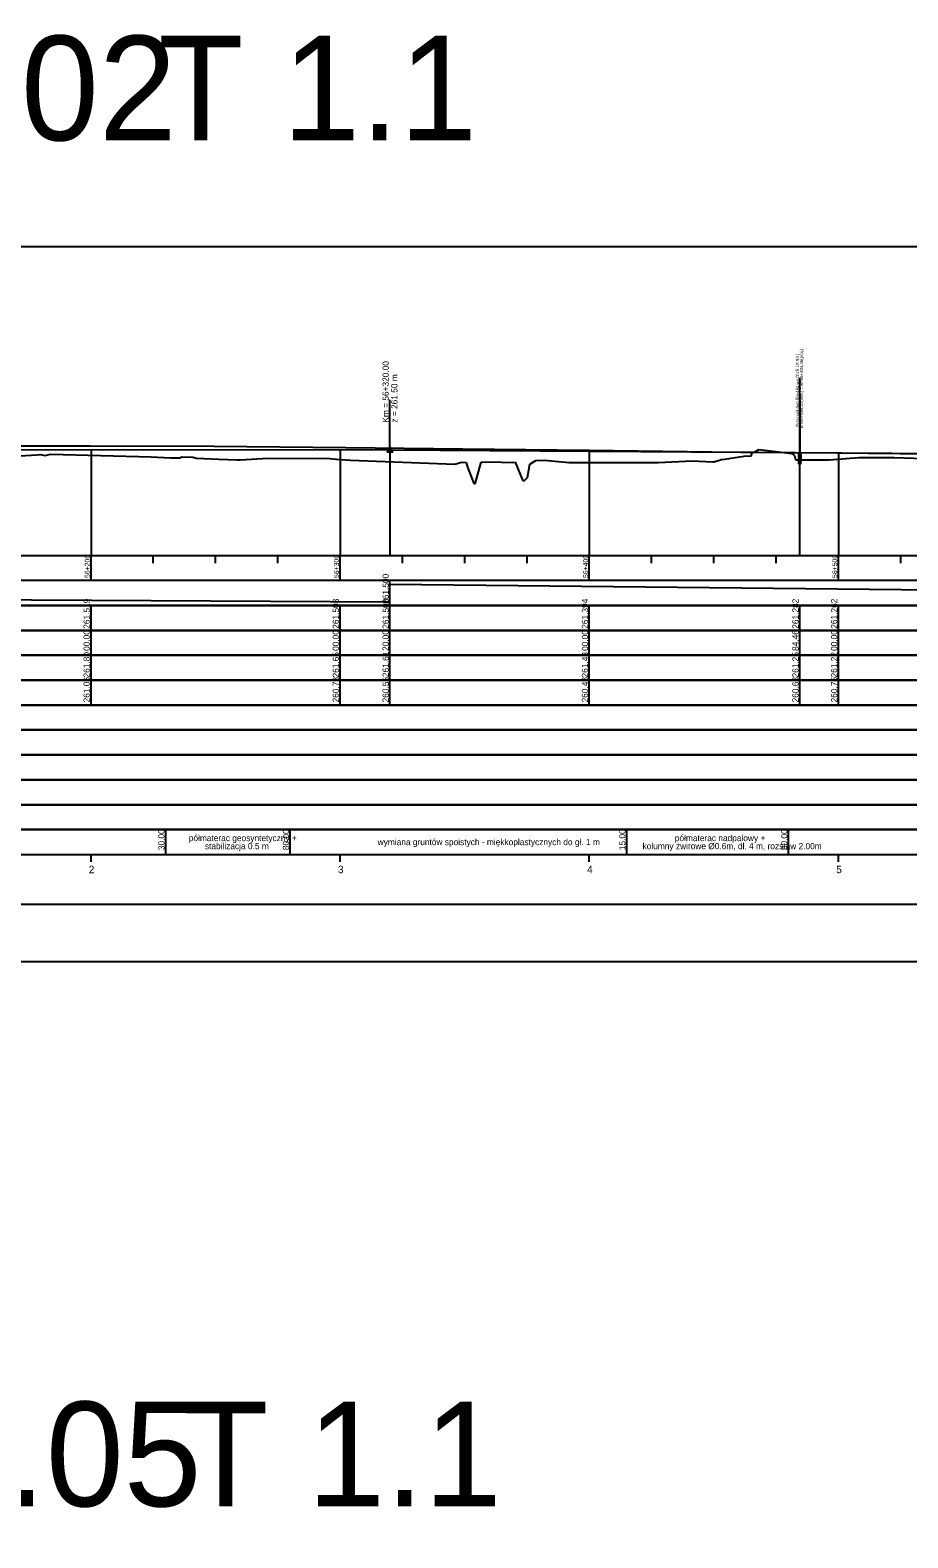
# Model space of a CAD drawing. Extents: x 6445630 to 6518227, y 5499240 to 5511716.
# Drawn here: x 6455407 to 6455759, y 5508735 to 5509341 of the extents above; entities that cross this region are included whole.
import ezdxf

# ---------------------------------------------------------------- set-up
doc = ezdxf.new("R2010")
doc.units = 0
for name, color, linetype in [('Default', 7, 'Continuous'), ('TOR_PROF-obiekty+opisy', 7, 'Continuous'), ('TOR_PROF-opisy pomocnicze', 7, 'Continuous'), ('TOR_PROF-tabelka-geometria T1', 7, 'Continuous'), ('TOR_PROF-tabelka-kilometracja', 7, 'Continuous'), ('TOR_PROF-tabelka-odleglosci T1', 7, 'Continuous'), ('TOR_PROF-tabelka-pochylenia proj T1', 7, 'Continuous'), ('TOR_PROF-tabelka-rodzaj rowu T1', 7, 'Continuous'), ('TOR_PROF-tabelka-rowyT1', 7, 'Continuous'), ('TOR_PROF-tabelka-rurociagi T1', 7, 'Continuous'), ('TOR_PROF-tabelka-rzedne istn T1', 7, 'Continuous'), ('TOR_PROF-tabelka-rzedne proj T1', 7, 'Continuous'), ('TOR_PROF-tabelka-teren istniejacy T1', 7, 'Continuous'), ('TOR_PROF-tabelka-warstwa ochronna T1', 7, 'Continuous'), ('TOR_PROF-tor istniejacy T1', 7, 'Continuous'), ('TOR_PROF-tor projektowany', 7, 'Continuous'), ('TOR_PROF-uklad odniesienia', 7, 'Continuous'), ('TOR_PROF-warstwa ochronna', 7, 'Continuous'), ('TOR_RAMKI-dodatkowe3', 7, 'Continuous'), ('TOR_RAMKI-MASKA WYCIECIA', 7, 'Continuous')]:
    doc.layers.add(name, color=color, linetype=linetype)

msp = doc.modelspace()

# ---------------------------------------------------------------- linework, layer by layer
at = {"layer": 'TOR_PROF-obiekty+opisy'}
for p, q in [((6455715.67, 5509129.74), (6455715.67, 5509201.14)), ((6455715.67, 5509192.14), (6455715.67, 5509171.14))]:
    msp.add_line(p, q, dxfattribs=at)
for points in [[(6455716.14, 5509170.78), (6455715.22, 5509170.78), (6455715.22, 5509166.7), (6455716.14, 5509166.7)], [(6455716.06, 5509170.24), (6455715.31, 5509170.24), (6455715.31, 5509167.24), (6455716.06, 5509167.24)]]:
    msp.add_lwpolyline(points, close=True, dxfattribs=at)
for points in [[(6455716.14, 5509166.7), (6455716.14, 5509170.78), (6455715.22, 5509170.78), (6455715.22, 5509166.7), (6455716.14, 5509166.7)], [(6455716.06, 5509167.24), (6455715.31, 5509167.24), (6455715.31, 5509170.24), (6455716.06, 5509170.24), (6455716.06, 5509167.24)]]:
    msp.add_lwpolyline(points, dxfattribs=at)
at = {"layer": 'TOR_PROF-opisy pomocnicze'}
msp.add_line((6455551.21, 5509172.24), (6455551.21, 5509192.24), dxfattribs=at)
msp.add_line((6455551.21, 5509172.24), (6455551.21, 5509192.24), dxfattribs=at)
msp.add_lwpolyline([(6455551.21, 5509173.24), (6455552.21, 5509171.24), (6455550.21, 5509171.24)], close=True, dxfattribs=at)
msp.add_lwpolyline([(6455551.21, 5509173.24), (6455552.21, 5509171.24), (6455550.21, 5509171.24)], close=True, dxfattribs=at)
at = {"layer": 'TOR_PROF-tabelka-geometria T1'}
for points in [[(6452331.21, 5508989.74), (6462728.4, 5508989.74)], [(6452331.21, 5508989.74), (6462731.21, 5508989.74)]]:
    msp.add_lwpolyline(points, dxfattribs=at)
at = {"layer": 'TOR_PROF-tabelka-kilometracja'}
for points in [[(6455431.21, 5509006.74), (6455431.21, 5509009.74)], [(6455531.21, 5509006.74), (6455531.21, 5509009.74)], [(6455631.21, 5509006.74), (6455631.21, 5509009.74)], [(6455731.21, 5509006.74), (6455731.21, 5509009.74)]]:
    msp.add_lwpolyline(points, dxfattribs=at)
at = {"layer": 'TOR_PROF-tabelka-odleglosci T1'}
msp.add_lwpolyline([(6452331.21, 5509089.74), (6462731.21, 5509089.74), (6462731.21, 5509099.74), (6452331.21, 5509099.74)], close=True, dxfattribs=at)
for points in [[(6455431.21, 5509089.74), (6455431.21, 5509099.74)], [(6455531.21, 5509089.74), (6455531.21, 5509099.74)], [(6455551.21, 5509089.74), (6455551.21, 5509099.74)], [(6455631.21, 5509089.74), (6455631.21, 5509099.74)], [(6455715.67, 5509089.74), (6455715.67, 5509099.74)], [(6455731.21, 5509089.74), (6455731.21, 5509099.74)]]:
    msp.add_lwpolyline(points, dxfattribs=at)
at = {"layer": 'TOR_PROF-tabelka-pochylenia proj T1'}
msp.add_lwpolyline([(6452331.21, 5509109.74), (6462731.21, 5509109.74), (6462731.21, 5509119.74), (6452331.21, 5509119.74)], close=True, dxfattribs=at)
for points in [[(6454281.21, 5509118.24), (6455551.21, 5509111.24)], [(6455551.21, 5509109.74), (6455551.21, 5509119.74)], [(6455551.21, 5509118.24), (6456231.21, 5509111.24)]]:
    msp.add_lwpolyline(points, dxfattribs=at)
at = {"layer": 'TOR_PROF-tabelka-rodzaj rowu T1'}
for points in [[(6452331.21, 5509049.74), (6462731.21, 5509049.74), (6462731.21, 5509059.74), (6452331.21, 5509059.74)], [(6452331.21, 5509029.74), (6462731.21, 5509029.74), (6462731.21, 5509039.74), (6452331.21, 5509039.74)]]:
    msp.add_lwpolyline(points, close=True, dxfattribs=at)
at = {"layer": 'TOR_PROF-tabelka-rowyT1'}
msp.add_lwpolyline([(6452331.21, 5509059.74), (6462731.21, 5509059.74), (6462731.21, 5509069.74), (6452331.21, 5509069.74)], close=True, dxfattribs=at)
at = {"layer": 'TOR_PROF-tabelka-rurociagi T1'}
msp.add_lwpolyline([(6452331.21, 5509039.74), (6462731.21, 5509039.74), (6462731.21, 5509049.74), (6452331.21, 5509049.74)], close=True, dxfattribs=at)
at = {"layer": 'TOR_PROF-tabelka-rzedne istn T1'}
msp.add_lwpolyline([(6452331.21, 5509079.74), (6462731.21, 5509079.74), (6462731.21, 5509089.74), (6452331.21, 5509089.74)], close=True, dxfattribs=at)
for points in [[(6455431.21, 5509079.74), (6455431.21, 5509089.74)], [(6455531.21, 5509079.74), (6455531.21, 5509089.74)], [(6455551.21, 5509079.74), (6455551.21, 5509089.74)], [(6455631.21, 5509079.74), (6455631.21, 5509089.74)], [(6455715.67, 5509079.74), (6455715.67, 5509089.74)], [(6455731.21, 5509079.74), (6455731.21, 5509089.74)], [(6455431.21, 5509069.74), (6455431.21, 5509079.74)], [(6455431.21, 5509069.74), (6455431.21, 5509079.74)], [(6455431.21, 5509069.74), (6455431.21, 5509079.74)], [(6455431.21, 5509069.74), (6455431.21, 5509079.74)], [(6455431.21, 5509069.74), (6455431.21, 5509079.74)], [(6455531.21, 5509069.74), (6455531.21, 5509079.74)], [(6455531.21, 5509069.74), (6455531.21, 5509079.74)], [(6455531.21, 5509069.74), (6455531.21, 5509079.74)], [(6455531.21, 5509069.74), (6455531.21, 5509079.74)], [(6455531.21, 5509069.74), (6455531.21, 5509079.74)], [(6455551.21, 5509069.74), (6455551.21, 5509079.74)], [(6455631.21, 5509069.74), (6455631.21, 5509079.74)], [(6455631.21, 5509069.74), (6455631.21, 5509079.74)], [(6455631.21, 5509069.74), (6455631.21, 5509079.74)], [(6455631.21, 5509069.74), (6455631.21, 5509079.74)], [(6455631.21, 5509069.74), (6455631.21, 5509079.74)], [(6455715.67, 5509069.74), (6455715.67, 5509079.74)], [(6455731.21, 5509069.74), (6455731.21, 5509079.74)], [(6455731.21, 5509069.74), (6455731.21, 5509079.74)], [(6455731.21, 5509069.74), (6455731.21, 5509079.74)], [(6455731.21, 5509069.74), (6455731.21, 5509079.74)], [(6455731.21, 5509069.74), (6455731.21, 5509079.74)]]:
    msp.add_lwpolyline(points, dxfattribs=at)
at = {"layer": 'TOR_PROF-tabelka-rzedne proj T1'}
msp.add_lwpolyline([(6452331.21, 5509099.74), (6462731.21, 5509099.74), (6462731.21, 5509109.74), (6452331.21, 5509109.74)], close=True, dxfattribs=at)
for points in [[(6455431.21, 5509099.74), (6455431.21, 5509109.74)], [(6455531.21, 5509099.74), (6455531.21, 5509109.74)], [(6455551.21, 5509099.74), (6455551.21, 5509109.74)], [(6455631.21, 5509099.74), (6455631.21, 5509109.74)], [(6455715.67, 5509099.74), (6455715.67, 5509109.74)], [(6455731.21, 5509099.74), (6455731.21, 5509109.74)]]:
    msp.add_lwpolyline(points, dxfattribs=at)
at = {"layer": 'TOR_PROF-tabelka-teren istniejacy T1'}
msp.add_lwpolyline([(6452331.21, 5509069.74), (6462731.21, 5509069.74), (6462731.21, 5509079.74), (6452331.21, 5509079.74)], close=True, dxfattribs=at)
msp.add_lwpolyline([(6452331.21, 5509069.74), (6462731.21, 5509069.74), (6462731.21, 5509079.74), (6452331.21, 5509079.74)], close=True, dxfattribs=at)
msp.add_lwpolyline([(6452331.21, 5509069.74), (6462731.21, 5509069.74), (6462731.21, 5509079.74), (6452331.21, 5509079.74)], close=True, dxfattribs=at)
msp.add_lwpolyline([(6452331.21, 5509069.74), (6462731.21, 5509069.74), (6462731.21, 5509079.74), (6452331.21, 5509079.74)], close=True, dxfattribs=at)
msp.add_lwpolyline([(6452331.21, 5509069.74), (6462731.21, 5509069.74), (6462731.21, 5509079.74), (6452331.21, 5509079.74)], close=True, dxfattribs=at)
at = {"layer": 'TOR_PROF-tabelka-warstwa ochronna T1'}
msp.add_lwpolyline([(6452331.21, 5509019.74), (6462731.21, 5509019.74), (6462731.21, 5509029.74), (6452331.21, 5509029.74)], close=True, dxfattribs=at)
at = {"layer": 'TOR_PROF-tor istniejacy T1'}
msp.add_lwpolyline([(6455781.2, 5509170.34), (6455730.52, 5509170.84), (6455680.26, 5509171.29), (6455631.15, 5509171.89), (6455580.46, 5509172.44), (6455533.44, 5509172.99), (6455480.48, 5509173.54), (6455430.92, 5509173.74), (6455379.79, 5509173.69), (6455329.04, 5509173.64), (6455279.53, 5509173.54), (6455230.64, 5509173.49), (6455180.11, 5509173.44), (6455131.36, 5509173.34), (6455080.92, 5509173.34), (6455031.47, 5509173.29)], dxfattribs=at)
at = {"layer": 'TOR_PROF-tor projektowany'}
for p, q in [((6454281.21, 5509173.24), (6455551.21, 5509172.24)), ((6454281.21, 5509173.24), (6455551.21, 5509172.24)), ((6455551.21, 5509172.24), (6456164.22, 5509168.18)), ((6455551.21, 5509172.24), (6456231.21, 5509167.74))]:
    msp.add_line(p, q, dxfattribs=at)
for points in [[(6455431.21, 5509172.33), (6455431.21, 5509134.74), (6455431.21, 5509129.74), (6455431.21, 5509129.74)], [(6455431.21, 5509172.33), (6455431.21, 5509134.74), (6455431.21, 5509129.74), (6455431.21, 5509129.74)], [(6455531.21, 5509172.25), (6455531.21, 5509134.74), (6455531.21, 5509129.74), (6455531.21, 5509129.74)], [(6455531.21, 5509172.25), (6455531.21, 5509134.74), (6455531.21, 5509129.74), (6455531.21, 5509129.74)], [(6455551.21, 5509172.24), (6455551.21, 5509134.74), (6455551.21, 5509129.74), (6455551.21, 5509129.74)], [(6455551.21, 5509172.24), (6455551.21, 5509134.74), (6455551.21, 5509129.74), (6455551.21, 5509129.74)], [(6455551.21, 5509172.24), (6455551.21, 5509134.74), (6455551.21, 5509129.74), (6455551.21, 5509129.74)], [(6455551.21, 5509172.24), (6455551.21, 5509134.74), (6455551.21, 5509129.74), (6455551.21, 5509129.74)], [(6455551.21, 5509172.24), (6455551.21, 5509134.74), (6455551.21, 5509129.74), (6455551.21, 5509129.74)], [(6455631.21, 5509171.71), (6455631.21, 5509134.74), (6455631.21, 5509129.74), (6455631.21, 5509129.74)], [(6455631.21, 5509171.71), (6455631.21, 5509134.74), (6455631.21, 5509129.74), (6455631.21, 5509129.74)], [(6455731.21, 5509171.04), (6455731.21, 5509134.74), (6455731.21, 5509129.74), (6455731.21, 5509129.74)], [(6455731.21, 5509171.04), (6455731.21, 5509134.74), (6455731.21, 5509129.74), (6455731.21, 5509129.74)]]:
    msp.add_lwpolyline(points, dxfattribs=at)
at = {"layer": 'TOR_PROF-uklad odniesienia'}
for p, q in [((6452331.21, 5509129.74), (6462731.21, 5509129.74)), ((6455431.21, 5509119.74), (6455431.21, 5509129.74)), ((6455456.21, 5509126.74), (6455456.21, 5509129.74)), ((6455481.21, 5509126.74), (6455481.21, 5509129.74)), ((6455506.21, 5509126.74), (6455506.21, 5509129.74)), ((6455531.21, 5509119.74), (6455531.21, 5509129.74)), ((6455556.21, 5509126.74), (6455556.21, 5509129.74)), ((6455581.21, 5509126.74), (6455581.21, 5509129.74)), ((6455606.21, 5509126.74), (6455606.21, 5509129.74)), ((6455631.21, 5509119.74), (6455631.21, 5509129.74)), ((6455656.21, 5509126.74), (6455656.21, 5509129.74)), ((6455681.21, 5509126.74), (6455681.21, 5509129.74)), ((6455706.21, 5509126.74), (6455706.21, 5509129.74)), ((6455731.21, 5509119.74), (6455731.21, 5509129.74)), ((6455756.21, 5509126.74), (6455756.21, 5509129.74))]:
    msp.add_line(p, q, dxfattribs=at)
at = {"layer": 'TOR_PROF-warstwa ochronna'}
msp.add_lwpolyline([(6452331.21, 5509009.74), (6462731.21, 5509009.74), (6462731.21, 5509019.74), (6452331.21, 5509019.74)], close=True, dxfattribs=at)
for points in [[(6455461.21, 5509009.74), (6455461.21, 5509019.74)], [(6455511.21, 5509009.74), (6455511.21, 5509019.74)], [(6455646.21, 5509009.74), (6455646.21, 5509019.74)], [(6455711.21, 5509009.74), (6455711.21, 5509019.74)]]:
    msp.add_lwpolyline(points, dxfattribs=at)
at = {"layer": 'TOR_RAMKI-dodatkowe3'}
for p, q in [((6455697.96, 5509171.5), (6455699.28, 5509172.36)), ((6455699.28, 5509172.36), (6455704.99, 5509171.68)), ((6455387.62, 5509168.87), (6455407.37, 5509170.11)), ((6455407.37, 5509170.11), (6455409.46, 5509170.21)), ((6455409.46, 5509170.21), (6455410.77, 5509170.35)), ((6455410.77, 5509170.35), (6455412.79, 5509169.88)), ((6455412.79, 5509169.88), (6455414.93, 5509170.47)), ((6455414.93, 5509170.47), (6455455.35, 5509169.37)), ((6455455.35, 5509169.37), (6455463.17, 5509168.98)), ((6455463.17, 5509168.98), (6455466.82, 5509169)), ((6455466.82, 5509169), (6455467.63, 5509169.43)), ((6455467.63, 5509169.43), (6455472.03, 5509169.31)), ((6455472.03, 5509169.31), (6455473.59, 5509168.86)), ((6455473.59, 5509168.86), (6455482.49, 5509168.45)), ((6455482.49, 5509168.45), (6455489.77, 5509168.16)), ((6455489.77, 5509168.16), (6455491.05, 5509168.17)), ((6455491.05, 5509168.17), (6455502.35, 5509168.91)), ((6455502.35, 5509168.91), (6455527.09, 5509168.76)), ((6455527.09, 5509168.76), (6455529.44, 5509168.52)), ((6455529.44, 5509168.52), (6455529.79, 5509168.49)), ((6455529.79, 5509168.49), (6455535.3, 5509168.1)), ((6455535.3, 5509168.1), (6455577.18, 5509166.53)), ((6455577.18, 5509166.53), (6455579.92, 5509167.25)), ((6455579.92, 5509167.25), (6455581.82, 5509167.2)), ((6455581.82, 5509167.2), (6455582.36, 5509165.21)), ((6455585.44, 5509158.51), (6455587.86, 5509167.31)), ((6455587.86, 5509167.31), (6455588.15, 5509167.28)), ((6455588.15, 5509167.28), (6455591.48, 5509167.38)), ((6455591.48, 5509167.38), (6455600.54, 5509167.1)), ((6455600.54, 5509167.1), (6455601.43, 5509167.23)), ((6455601.43, 5509167.23), (6455604.56, 5509159.81)), ((6455606.36, 5509161.08), (6455607.37, 5509166.53)), ((6455607.37, 5509166.53), (6455609.76, 5509167.98)), ((6455609.76, 5509167.98), (6455613.23, 5509168.04)), ((6455613.23, 5509168.04), (6455613.26, 5509168.04)), ((6455613.26, 5509168.04), (6455622.99, 5509167.19)), ((6455622.99, 5509167.19), (6455626.99, 5509167.16)), ((6455626.99, 5509167.16), (6455649.61, 5509167.09)), ((6455649.61, 5509167.09), (6455652.4, 5509167.11)), ((6455652.4, 5509167.11), (6455656.88, 5509167.16)), ((6455656.88, 5509167.16), (6455658.87, 5509167.13)), ((6455658.87, 5509167.13), (6455672.65, 5509167.78)), ((6455672.65, 5509167.78), (6455678.02, 5509167.6)), ((6455678.02, 5509167.6), (6455680.89, 5509167.42)), ((6455680.89, 5509167.42), (6455681.05, 5509167.44)), ((6455681.05, 5509167.44), (6455681.16, 5509167.42)), ((6455681.16, 5509167.42), (6455683.91, 5509168.17)), ((6455683.91, 5509168.17), (6455684.19, 5509168.47)), ((6455684.19, 5509168.47), (6455684.52, 5509168.35)), ((6455684.52, 5509168.35), (6455694.21, 5509169.76)), ((6455694.21, 5509169.76), (6455696.11, 5509169.68)), ((6455696.11, 5509169.68), (6455696.63, 5509170.97)), ((6455696.63, 5509170.97), (6455697.96, 5509171.5)), ((6455704.99, 5509171.68), (6455712.51, 5509170.72)), ((6455712.51, 5509170.72), (6455713.49, 5509169.9)), ((6455713.49, 5509169.9), (6455714.01, 5509168.3)), ((6455714.01, 5509168.3), (6455714.4, 5509168.15)), ((6455714.4, 5509168.15), (6455727.39, 5509168.17)), ((6455727.39, 5509168.17), (6455739.43, 5509169.1)), ((6455739.43, 5509169.1), (6455753.59, 5509169.12)), ((6455753.59, 5509169.12), (6455765.48, 5509168.78)), ((6455582.36, 5509165.21), (6455584.85, 5509158.68)), ((6455604.56, 5509159.81), (6455605.34, 5509160.01)), ((6455605.34, 5509160.01), (6455606.36, 5509161.08)), ((6455584.85, 5509158.68), (6455585.23, 5509158.66)), ((6455585.23, 5509158.66), (6455585.44, 5509158.51))]:
    msp.add_line(p, q, dxfattribs=at)
at = {"layer": 'TOR_RAMKI-MASKA WYCIECIA'}
msp.add_lwpolyline([(6454268.59, 5508966.75), (6456248.59, 5508966.75), (6456248.59, 5509253.75), (6454268.59, 5509253.75)], close=True, dxfattribs=at)

# ---------------------------------------------------------------- texts
at = {"layer": 'Default'}
for p in [(6455430.92, 5509173.74), (6455480.48, 5509173.54), (6455533.44, 5509172.99), (6455580.46, 5509172.44), (6455631.15, 5509171.89), (6455680.26, 5509171.29), (6455730.52, 5509170.84)]:
    msp.add_text('+', height=0.001, dxfattribs=at).set_placement(p)
at = {"layer": 'TOR_PROF-obiekty+opisy'}
for s, p in [('  Przepust (km 56+484 wg DUŚ LK 93 )', (6455715.34, 5509180.58)), (' km56+486,32(istn.) = km56+484,46(proj.) ', (6455716.96, 5509180.58))]:
    msp.add_text(s, height=1.25, rotation=90, dxfattribs=at).set_placement(p)
at = {"layer": 'TOR_PROF-opisy pomocnicze'}
for s, p in [('Km = 56+320.00', (6455550.71, 5509183.14)), ('Km = 56+320.00', (6455550.71, 5509183.14)), ('z = 261.50 m', (6455554.21, 5509183.14)), ('z = 261.50 m', (6455554.21, 5509183.14))]:
    msp.add_text(s, height=2.5, rotation=90, dxfattribs=at).set_placement(p)
at = {"layer": 'TOR_PROF-tabelka-kilometracja'}
for s, p in [('2', (6455430.33, 5509002.24)), ('3', (6455530.32, 5509002.24)), ('4', (6455630.32, 5509002.24)), ('5', (6455730.31, 5509002.24))]:
    msp.add_text(s, height=3, dxfattribs=at).set_placement(p)
at = {"layer": 'TOR_PROF-tabelka-odleglosci T1'}
for s, p in [('00.00', (6455430.71, 5509091.48)), ('00.00', (6455530.71, 5509091.48)), ('20.00', (6455550.71, 5509091.48)), ('00.00', (6455630.71, 5509091.48)), ('84.46', (6455715.17, 5509091.47)), ('00.00', (6455730.71, 5509091.48))]:
    msp.add_text(s, height=2.5, rotation=90, dxfattribs=at).set_placement(p)
at = {"layer": 'TOR_PROF-tabelka-pochylenia proj T1'}
msp.add_text('261.500', height=2.5, rotation=90, dxfattribs=at).set_placement((6455550.71, 5509110.37))
at = {"layer": 'TOR_PROF-tabelka-rzedne istn T1'}
for s, p in [('261.80', (6455430.71, 5509080.8)), ('261.65', (6455530.71, 5509080.8)), ('261.61', (6455550.71, 5509080.97)), ('261.43', (6455630.71, 5509080.8)), ('261.25', (6455715.17, 5509080.8)), ('261.22', (6455730.71, 5509080.81)), ('261.06', (6455430.71, 5509070.8)), ('260.73', (6455530.71, 5509070.8)), ('260.55', (6455550.71, 5509070.8)), ('260.48', (6455630.71, 5509070.8)), ('260.68', (6455715.17, 5509070.8)), ('260.75', (6455730.71, 5509070.8))]:
    msp.add_text(s, height=2.5, rotation=90, dxfattribs=at).set_placement(p)
at = {"layer": 'TOR_PROF-tabelka-rzedne proj T1'}
for s, p in [('261.519', (6455430.71, 5509100.37)), ('261.503', (6455530.71, 5509100.37)), ('261.500', (6455550.71, 5509100.37)), ('261.394', (6455630.71, 5509100.37)), ('261.282', (6455715.17, 5509100.38)), ('261.262', (6455730.71, 5509100.38))]:
    msp.add_text(s, height=2.5, rotation=90, dxfattribs=at).set_placement(p)
at = {"layer": 'TOR_PROF-uklad odniesienia'}
for s, p in [('Rysunek 4.02', (6455122.15, 5509296.49)), ('T 1.1', (6455458.15, 5509296.49)), ('Rysunek 4.05', (6455132.15, 5508748.03)), ('T 1.1', (6455468.15, 5508748.03))]:
    msp.add_text(s, height=42, dxfattribs=at).set_placement(p)
for s, p in [('56+200', (6455430.71, 5509120.76)), ('56+300', (6455530.71, 5509120.76)), ('56+400', (6455630.71, 5509120.76)), ('56+500', (6455730.71, 5509120.76))]:
    msp.add_text(s, height=2, rotation=90, dxfattribs=at).set_placement(p)
at = {"layer": 'TOR_PROF-warstwa ochronna'}
for s, p in [('30.00', (6455460.71, 5509011.48)), ('80.00', (6455510.71, 5509011.48)), ('15.00', (6455645.71, 5509011.48)), ('80.00', (6455710.71, 5509011.48))]:
    msp.add_text(s, height=2.5, rotation=90, dxfattribs=at).set_placement(p)
for s, p in [('półmaterac geosyntetyczny +', (6455470.44, 5509015.1)), ('stabilizacja 0.5 m', (6455476.92, 5509011.87)), ('wymiana gruntów spoistych - miękkoplastycznych do gł. 1 m', (6455546.26, 5509013.49)), ('kolumny żwirowe Ø0.6m, dł. 4 m, rozstaw 2.00m', (6455652.58, 5509011.87)), ('półmaterac nadpalowy +', (6455665.51, 5509015.1))]:
    msp.add_text(s, height=2.5, dxfattribs=at).set_placement(p)

doc.saveas('drawing.dxf')
